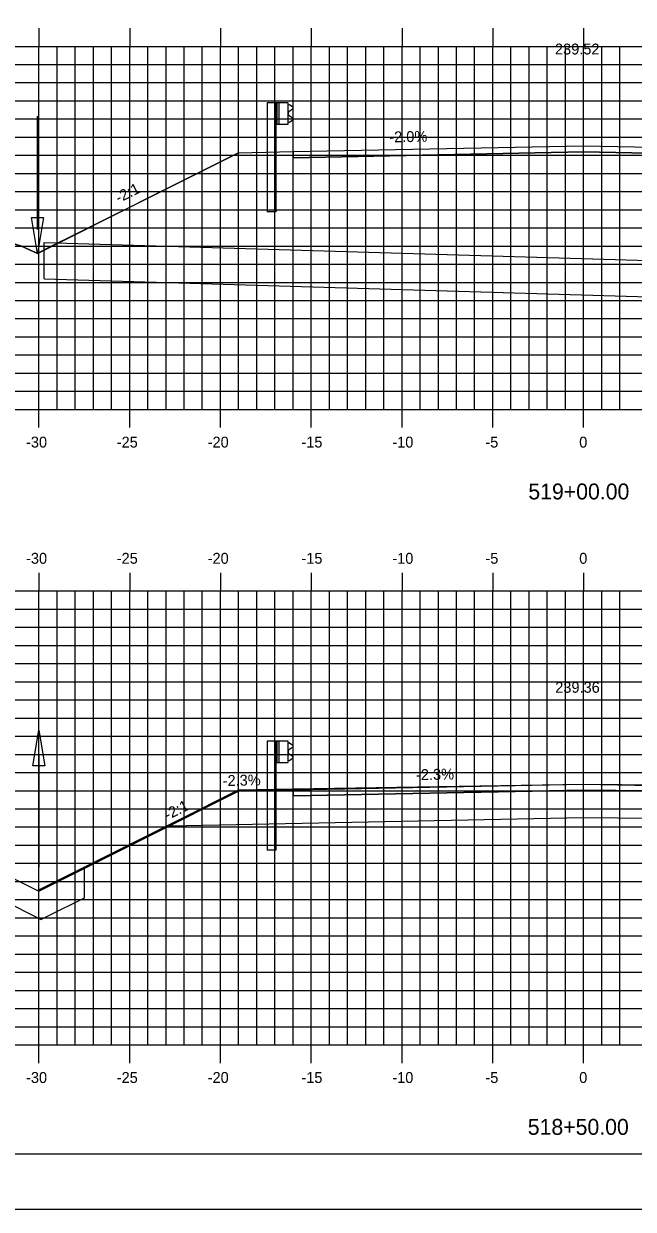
# Model space of a CAD drawing. Extents: x 1170543 to 1177585, y 609599 to 610623.
# Drawn here: x 1173995.7 to 1174029.3, y 609598.8 to 609664.1 of the extents above; entities that cross this region are included whole.
import ezdxf

# ---------------------------------------------------------------- set-up
doc = ezdxf.new("R2010")
doc.units = 0
for name, color, linetype in [('ANNOTATION', 7, 'Continuous'), ('BORDER', 7, 'Continuous'), ('D_Drainage_Culvert', 7, 'Continuous'), ('D_Drainage_Ditch_Line', 7, 'Continuous'), ('D_Guardrail_Beam_Lt', 7, 'Continuous'), ('D_Roadway_Centerline', 7, 'Continuous'), ('D_Roadway_Centerline_Text', 7, 'Continuous'), ('D_Roadway_Edge_Shoulder', 7, 'Continuous'), ('D_Roadway_Edge_TW', 7, 'Continuous'), ('D_Roadway_Pavement', 7, 'Continuous'), ('D_Roadway_SlopeLines', 7, 'Continuous'), ('D_Roadway_SubGrade', 7, 'Continuous'), ('H_V ANNOTATION', 7, 'Continuous'), ('MAJOR', 7, 'Continuous'), ('MINOR', 7, 'Continuous'), ('PATTERNING', 7, 'Continuous'), ('PLOT BOUNDARY', 7, 'Continuous'), ('S_Roadway_Centerline', 7, 'Continuous'), ('SHADING', 7, 'Continuous')]:
    doc.layers.add(name, color=color, linetype=linetype)

msp = doc.modelspace()

# ---------------------------------------------------------------- linework, layer by layer
at = {"layer": 'ANNOTATION'}
for p, q in [((1173994.024, 609617.589), (1173996.524, 609616.339)), ((1173999.024, 609617.589), (1173999.024, 609615.958)), ((1173999.024, 609615.958), (1173997.024, 609614.958)), ((1173997.024, 609614.958), (1173996.655, 609614.774))]:
    msp.add_line(p, q, dxfattribs=at)
msp.add_lwpolyline([(1173994.024, 609617.589), (1173994.024, 609616.089), (1173996.024, 609615.089), (1173996.655, 609614.774)], dxfattribs=at)
at = {"layer": 'BORDER'}
msp.add_line((1173951.531, 609601.872), (1174111.531, 609601.872), dxfattribs=at)
at = {"layer": 'D_Drainage_Culvert'}
for p, q in [((1173996.81, 609652.072), (1174060.21, 609650.172)), ((1173996.81, 609650.072), (1173996.81, 609652.072)), ((1173996.81, 609650.072), (1174060.21, 609648.172))]:
    msp.add_line(p, q, dxfattribs=at)
at = {"layer": 'D_Drainage_Ditch_Line'}
for p, q in [((1173996.447, 609652.782), (1173996.448, 609659.026)), ((1173996.524, 609623.895), (1173996.524, 609617.652))]:
    msp.add_line(p, q, dxfattribs=at)
for points in [[(1173996.119, 609653.439), (1173996.775, 609653.439), (1173996.447, 609651.47)], [(1173996.852, 609623.239), (1173996.196, 609623.239), (1173996.524, 609625.207)]]:
    msp.add_lwpolyline(points, close=True, dxfattribs=at)
at = {"layer": 'D_Guardrail_Beam_Lt'}
for p, q in [((1174009.101, 609659.757), (1174009.101, 609653.757)), ((1174009.572, 609659.757), (1174009.101, 609659.757)), ((1174010.259, 609659.757), (1174009.572, 609659.757)), ((1174009.572, 609659.757), (1174009.572, 609658.591)), ((1174009.634, 609659.757), (1174009.634, 609658.591)), ((1174009.739, 609659.757), (1174009.739, 609658.591)), ((1174010.259, 609658.591), (1174010.259, 609659.757)), ((1174010.259, 609659.674), (1174010.334, 609659.659)), ((1174010.264, 609659.209), (1174010.264, 609659.139)), ((1174010.493, 609659.41), (1174010.298, 609659.273)), ((1174010.349, 609659.653), (1174010.493, 609659.553)), ((1174009.572, 609658.591), (1174010.259, 609658.591)), ((1174009.593, 609653.757), (1174009.593, 609658.591)), ((1174010.334, 609658.689), (1174010.259, 609658.674)), ((1174010.298, 609659.074), (1174010.493, 609658.938)), ((1174010.493, 609658.795), (1174010.349, 609658.695)), ((1174009.593, 609653.757), (1174009.101, 609653.757)), ((1174009.101, 609624.598), (1174009.101, 609618.598)), ((1174009.572, 609624.598), (1174009.101, 609624.598)), ((1174010.259, 609624.598), (1174009.572, 609624.598)), ((1174009.572, 609624.598), (1174009.572, 609623.432)), ((1174009.634, 609624.598), (1174009.634, 609623.432)), ((1174009.739, 609624.598), (1174009.739, 609623.432)), ((1174010.259, 609623.432), (1174010.259, 609624.598)), ((1174010.259, 609624.515), (1174010.334, 609624.5)), ((1174010.264, 609624.05), (1174010.264, 609623.98)), ((1174010.493, 609624.251), (1174010.298, 609624.114)), ((1174010.298, 609623.916), (1174010.493, 609623.779)), ((1174010.349, 609624.494), (1174010.493, 609624.394)), ((1174009.572, 609623.432), (1174010.259, 609623.432)), ((1174009.593, 609618.598), (1174009.593, 609623.432)), ((1174010.334, 609623.53), (1174010.259, 609623.515)), ((1174010.493, 609623.636), (1174010.349, 609623.536)), ((1174009.593, 609618.598), (1174009.101, 609618.598))]:
    msp.add_line(p, q, dxfattribs=at)
for centre, major_axis, start_param, end_param in [((1174010.343, 609659.209), (-0.0789, 0), 5.323254, 6.283185), ((1174010.326, 609659.619), (0.0417, 0), 0.959931, 1.376053), ((1174010.443, 609659.481), (0.0877, 0), 5.323254, 7.243116), ((1174010.343, 609659.139), (-0.0789, 0), 6.283185, 7.243116), ((1174010.326, 609658.729), (0.0417, 0), 4.907132, 5.323254), ((1174010.443, 609658.867), (0.0877, 0), 5.323254, 7.243116), ((1174010.343, 609624.05), (-0.0789, 0), 5.323254, 6.283185), ((1174010.343, 609623.98), (-0.0789, 0), 6.283185, 7.243116), ((1174010.326, 609624.46), (0.0417, 0), 0.959931, 1.376053), ((1174010.443, 609624.322), (0.0877, 0), 5.323254, 7.243116), ((1174010.326, 609623.57), (0.0417, 0), 4.907132, 5.323254), ((1174010.443, 609623.708), (0.0877, 0), 5.323254, 7.243116)]:
    msp.add_ellipse(centre, major_axis=major_axis, ratio=0.995501, start_param=start_param, end_param=end_param, dxfattribs=at)
at = {"layer": 'D_Roadway_Centerline'}
for p, q in [((1174010.53, 609621.913), (1174026.53, 609622.233)), ((1174026.53, 609622.233), (1174042.53, 609622.073)), ((1174002.69, 609619.423), (1174007.53, 609621.843)), ((1174007.53, 609621.843), (1174010.53, 609621.913)), ((1173996.524, 609616.339), (1174002.69, 609619.423))]:
    msp.add_line(p, q, dxfattribs=at)
msp.add_lwpolyline([(1173992.948, 609652.403), (1173993.823, 609652.323), (1173994.698, 609652.141), (1173995.573, 609651.857), (1173996.447, 609651.47), (1174002.669, 609654.581), (1174007.53, 609657.012), (1174010.53, 609657.072), (1174026.53, 609657.392), (1174042.53, 609657.072), (1174045.53, 609657.012), (1174050.391, 609654.581), (1174056.613, 609651.47), (1174062.834, 609648.36)], dxfattribs=at)
at = {"layer": 'D_Roadway_Edge_Shoulder'}
for points in [[(1174010.53, 609657.072), (1174010.53, 609656.738)], [(1174010.53, 609621.913), (1174010.53, 609621.579)]]:
    msp.add_lwpolyline(points, dxfattribs=at)
at = {"layer": 'D_Roadway_Edge_TW'}
for points in [[(1174010.53, 609656.738), (1174010.53, 609657.072), (1174026.53, 609657.392), (1174042.53, 609657.072), (1174042.53, 609656.738), (1174026.53, 609657.058)], [(1174010.53, 609621.579), (1174010.53, 609621.913), (1174026.53, 609622.233), (1174042.53, 609622.073), (1174042.53, 609621.739), (1174026.53, 609621.899)]]:
    msp.add_lwpolyline(points, close=True, dxfattribs=at)
at = {"layer": 'D_Roadway_Pavement'}
for points in [[(1174010.53, 609656.738), (1174010.53, 609656.738), (1174026.53, 609657.058), (1174042.53, 609656.738), (1174042.53, 609656.738), (1174026.53, 609657.058)], [(1174010.53, 609621.579), (1174010.53, 609621.579), (1174026.53, 609621.899), (1174042.53, 609621.739), (1174042.53, 609621.739), (1174026.53, 609621.899)]]:
    msp.add_lwpolyline(points, close=True, dxfattribs=at)
for points in [[(1174010.53, 609656.738), (1174010.53, 609656.738)], [(1174010.53, 609656.738), (1174010.53, 609656.738)], [(1174010.53, 609621.579), (1174010.53, 609621.579)], [(1174010.53, 609621.579), (1174010.53, 609621.579)]]:
    msp.add_lwpolyline(points, dxfattribs=at)
at = {"layer": 'D_Roadway_SlopeLines'}
msp.add_line((1173996.447, 609616.378), (1173996.524, 609616.339), dxfattribs=at)
for points in [[(1174007.53, 609657.012), (1173996.447, 609651.47)], [(1173996.447, 609651.47), (1173995.573, 609651.857), (1173994.698, 609652.141), (1173993.823, 609652.323), (1173992.948, 609652.403)], [(1174007.53, 609621.843), (1173996.524, 609616.339)]]:
    msp.add_lwpolyline(points, dxfattribs=at)
at = {"layer": 'D_Roadway_SubGrade'}
for p, q in [((1174007.53, 609621.843), (1174002.69, 609619.423)), ((1174010.53, 609621.913), (1174007.53, 609621.843)), ((1174010.53, 609620.079), (1174010.53, 609621.913)), ((1174010.53, 609621.579), (1174026.53, 609621.899)), ((1174010.53, 609620.079), (1174010.53, 609621.579)), ((1174026.53, 609621.899), (1174042.53, 609621.739))]:
    msp.add_line(p, q, dxfattribs=at)
at = {"layer": 'MAJOR'}
for p, q in [((1173996.53, 609663.874), (1173996.53, 609662.872)), ((1174001.53, 609663.874), (1174001.53, 609662.872)), ((1174006.53, 609663.874), (1174006.53, 609662.872)), ((1174011.53, 609663.874), (1174011.53, 609662.872)), ((1174016.53, 609663.874), (1174016.53, 609662.872)), ((1174021.53, 609663.874), (1174021.53, 609662.872)), ((1174026.53, 609663.874), (1174026.53, 609662.872)), ((1173956.53, 609662.872), (1174096.53, 609662.872)), ((1173956.53, 609662.872), (1174096.53, 609662.872)), ((1173996.53, 609642.872), (1173996.53, 609662.872)), ((1174001.53, 609642.872), (1174001.53, 609662.872)), ((1174006.53, 609642.872), (1174006.53, 609662.872)), ((1174011.53, 609642.872), (1174011.53, 609662.872)), ((1174016.53, 609642.872), (1174016.53, 609662.872)), ((1174021.53, 609642.872), (1174021.53, 609662.872)), ((1174026.53, 609642.872), (1174026.53, 609662.872)), ((1173956.53, 609657.872), (1174096.53, 609657.872)), ((1173956.53, 609652.872), (1174096.53, 609652.872)), ((1173956.53, 609647.872), (1174096.53, 609647.872)), ((1173956.53, 609642.872), (1174096.53, 609642.872)), ((1173956.53, 609642.872), (1174096.53, 609642.872)), ((1173996.53, 609641.87), (1173996.53, 609642.872)), ((1174001.53, 609641.87), (1174001.53, 609642.872)), ((1174006.53, 609641.87), (1174006.53, 609642.872)), ((1174011.53, 609641.87), (1174011.53, 609642.872)), ((1174016.53, 609641.87), (1174016.53, 609642.872)), ((1174021.53, 609641.87), (1174021.53, 609642.872)), ((1174026.53, 609641.87), (1174026.53, 609642.872)), ((1173996.53, 609633.874), (1173996.53, 609632.872)), ((1174001.53, 609633.874), (1174001.53, 609632.872)), ((1174006.53, 609633.874), (1174006.53, 609632.872)), ((1174011.53, 609633.874), (1174011.53, 609632.872)), ((1174016.53, 609633.874), (1174016.53, 609632.872)), ((1174021.53, 609633.874), (1174021.53, 609632.872)), ((1174026.53, 609633.874), (1174026.53, 609632.872)), ((1173956.53, 609632.872), (1174096.53, 609632.872)), ((1173956.53, 609632.872), (1174096.53, 609632.872)), ((1173996.53, 609607.872), (1173996.53, 609632.872)), ((1174001.53, 609607.872), (1174001.53, 609632.872)), ((1174006.53, 609607.872), (1174006.53, 609632.872)), ((1174011.53, 609607.872), (1174011.53, 609632.872)), ((1174016.53, 609607.872), (1174016.53, 609632.872)), ((1174021.53, 609607.872), (1174021.53, 609632.872)), ((1174026.53, 609607.872), (1174026.53, 609632.872)), ((1173956.53, 609627.872), (1174096.53, 609627.872)), ((1173956.53, 609622.872), (1174096.53, 609622.872)), ((1173956.53, 609617.872), (1174096.53, 609617.872)), ((1173956.53, 609612.872), (1174096.53, 609612.872)), ((1173956.53, 609607.872), (1174096.53, 609607.872)), ((1173956.53, 609607.872), (1174096.53, 609607.872)), ((1173996.53, 609606.87), (1173996.53, 609607.872)), ((1174001.53, 609606.87), (1174001.53, 609607.872)), ((1174006.53, 609606.87), (1174006.53, 609607.872)), ((1174011.53, 609606.87), (1174011.53, 609607.872)), ((1174016.53, 609606.87), (1174016.53, 609607.872)), ((1174021.53, 609606.87), (1174021.53, 609607.872)), ((1174026.53, 609606.87), (1174026.53, 609607.872))]:
    msp.add_line(p, q, dxfattribs=at)
at = {"layer": 'MINOR'}
for p, q in [((1173997.53, 609642.872), (1173997.53, 609662.872)), ((1173998.53, 609642.872), (1173998.53, 609662.872)), ((1173999.53, 609642.872), (1173999.53, 609662.872)), ((1174000.53, 609642.872), (1174000.53, 609662.872)), ((1174002.53, 609642.872), (1174002.53, 609662.872)), ((1174003.53, 609642.872), (1174003.53, 609662.872)), ((1174004.53, 609642.872), (1174004.53, 609662.872)), ((1174005.53, 609642.872), (1174005.53, 609662.872)), ((1174007.53, 609642.872), (1174007.53, 609662.872)), ((1174008.53, 609642.872), (1174008.53, 609662.872)), ((1174009.53, 609642.872), (1174009.53, 609662.872)), ((1174010.53, 609642.872), (1174010.53, 609662.872)), ((1174012.53, 609642.872), (1174012.53, 609662.872)), ((1174013.53, 609642.872), (1174013.53, 609662.872)), ((1174014.53, 609642.872), (1174014.53, 609662.872)), ((1174015.53, 609642.872), (1174015.53, 609662.872)), ((1174017.53, 609642.872), (1174017.53, 609662.872)), ((1174018.53, 609642.872), (1174018.53, 609662.872)), ((1174019.53, 609642.872), (1174019.53, 609662.872)), ((1174020.53, 609642.872), (1174020.53, 609662.872)), ((1174022.53, 609642.872), (1174022.53, 609662.872)), ((1174023.53, 609642.872), (1174023.53, 609662.872)), ((1174024.53, 609642.872), (1174024.53, 609662.872)), ((1174025.53, 609642.872), (1174025.53, 609662.872)), ((1174027.53, 609642.872), (1174027.53, 609662.872)), ((1174028.53, 609642.872), (1174028.53, 609662.872)), ((1173956.53, 609661.872), (1174096.53, 609661.872)), ((1173956.53, 609660.872), (1174096.53, 609660.872)), ((1173956.53, 609659.872), (1174096.53, 609659.872)), ((1173956.53, 609658.872), (1174096.53, 609658.872)), ((1173956.53, 609656.872), (1174096.53, 609656.872)), ((1173956.53, 609655.872), (1174096.53, 609655.872)), ((1173956.53, 609654.872), (1174096.53, 609654.872)), ((1173956.53, 609653.872), (1174096.53, 609653.872)), ((1173956.53, 609651.872), (1174096.53, 609651.872)), ((1173956.53, 609650.872), (1174096.53, 609650.872)), ((1173956.53, 609649.872), (1174096.53, 609649.872)), ((1173956.53, 609648.872), (1174096.53, 609648.872)), ((1173956.53, 609646.872), (1174096.53, 609646.872)), ((1173956.53, 609645.872), (1174096.53, 609645.872)), ((1173956.53, 609644.872), (1174096.53, 609644.872)), ((1173956.53, 609643.872), (1174096.53, 609643.872)), ((1173997.53, 609607.872), (1173997.53, 609632.872)), ((1173998.53, 609607.872), (1173998.53, 609632.872)), ((1173999.53, 609607.872), (1173999.53, 609632.872)), ((1174000.53, 609607.872), (1174000.53, 609632.872)), ((1174002.53, 609607.872), (1174002.53, 609632.872)), ((1174003.53, 609607.872), (1174003.53, 609632.872)), ((1174004.53, 609607.872), (1174004.53, 609632.872)), ((1174005.53, 609607.872), (1174005.53, 609632.872)), ((1174007.53, 609607.872), (1174007.53, 609632.872)), ((1174008.53, 609607.872), (1174008.53, 609632.872)), ((1174009.53, 609607.872), (1174009.53, 609632.872)), ((1174010.53, 609607.872), (1174010.53, 609632.872)), ((1174012.53, 609607.872), (1174012.53, 609632.872)), ((1174013.53, 609607.872), (1174013.53, 609632.872)), ((1174014.53, 609607.872), (1174014.53, 609632.872)), ((1174015.53, 609607.872), (1174015.53, 609632.872)), ((1174017.53, 609607.872), (1174017.53, 609632.872)), ((1174018.53, 609607.872), (1174018.53, 609632.872)), ((1174019.53, 609607.872), (1174019.53, 609632.872)), ((1174020.53, 609607.872), (1174020.53, 609632.872)), ((1174022.53, 609607.872), (1174022.53, 609632.872)), ((1174023.53, 609607.872), (1174023.53, 609632.872)), ((1174024.53, 609607.872), (1174024.53, 609632.872)), ((1174025.53, 609607.872), (1174025.53, 609632.872)), ((1174027.53, 609607.872), (1174027.53, 609632.872)), ((1174028.53, 609607.872), (1174028.53, 609632.872)), ((1173956.53, 609631.872), (1174096.53, 609631.872)), ((1173956.53, 609630.872), (1174096.53, 609630.872)), ((1173956.53, 609629.872), (1174096.53, 609629.872)), ((1173956.53, 609628.872), (1174096.53, 609628.872)), ((1173956.53, 609626.872), (1174096.53, 609626.872)), ((1173956.53, 609625.872), (1174096.53, 609625.872)), ((1173956.53, 609624.872), (1174096.53, 609624.872)), ((1173956.53, 609623.872), (1174096.53, 609623.872)), ((1173956.53, 609621.872), (1174096.53, 609621.872)), ((1173956.53, 609620.872), (1174096.53, 609620.872)), ((1173956.53, 609619.872), (1174096.53, 609619.872)), ((1173956.53, 609618.872), (1174096.53, 609618.872)), ((1173956.53, 609616.872), (1174096.53, 609616.872)), ((1173956.53, 609615.872), (1174096.53, 609615.872)), ((1173956.53, 609614.872), (1174096.53, 609614.872)), ((1173956.53, 609613.872), (1174096.53, 609613.872)), ((1173956.53, 609611.872), (1174096.53, 609611.872)), ((1173956.53, 609610.872), (1174096.53, 609610.872)), ((1173956.53, 609609.872), (1174096.53, 609609.872)), ((1173956.53, 609608.872), (1174096.53, 609608.872))]:
    msp.add_line(p, q, dxfattribs=at)
at = {"layer": 'PATTERNING'}
msp.add_lwpolyline([(1173996.524, 609616.339), (1173998.524, 609617.339), (1173999.024, 609617.589)], dxfattribs=at)
at = {"layer": 'PLOT BOUNDARY'}
msp.add_lwpolyline([(1173943.437, 609598.813), (1174113.437, 609598.813), (1174113.437, 609708.813), (1173943.437, 609708.813)], close=True, dxfattribs=at)
at = {"layer": 'S_Roadway_Centerline'}
for points in [[(1173995.574, 609651.857), (1173996.448, 609651.471), (1173997.198, 609651.86), (1173997.833, 609652.175), (1173997.855, 609652.173), (1173997.855, 609652.173), (1173997.855, 609652.173), (1173997.855, 609652.173), (1173997.855, 609652.173), (1173997.855, 609652.173), (1173997.855, 609652.173), (1173997.855, 609652.173), (1173997.855, 609652.173), (1174004.145, 609655.318), (1174004.145, 609655.318), (1174007.53, 609657.011), (1174007.53, 609657.011), (1174010.53, 609657.071), (1174010.53, 609657.071), (1174026.53, 609657.391), (1174026.53, 609657.391), (1174042.53, 609657.071)], [(1173991.629, 609618.787), (1173996.448, 609616.377), (1173996.448, 609616.377), (1174002.834, 609619.57), (1174002.834, 609619.57), (1174002.834, 609619.57), (1174002.834, 609619.57), (1174004.199, 609620.253), (1174004.199, 609620.253), (1174007.53, 609621.918), (1174007.53, 609621.918), (1174007.53, 609621.918), (1174010.53, 609621.978), (1174026.53, 609622.232), (1174026.53, 609622.232), (1174026.531, 609622.232), (1174042.53, 609621.912)]]:
    msp.add_lwpolyline(points, dxfattribs=at)
at = {"layer": 'SHADING'}
msp.add_lwpolyline([(1174003.732, 609619.943), (1174026.53, 609620.399), (1174049.211, 609620.173)], dxfattribs=at)

# ---------------------------------------------------------------- texts
at = {"layer": 'ANNOTATION'}
for s, rotation, p in [('-2.0%', 1.14576, (1174015.833, 609657.578)), ('-2:1', 26.56505, (1174000.918, 609654.223)), ('-2.3%', 1.33666, (1174006.657, 609622.122)), ('-2.3%', 1.14576, (1174017.307, 609622.448)), ('-2:1', 26.56505, (1174003.611, 609620.231))]:
    msp.add_text(s, height=0.6, rotation=rotation, dxfattribs=at).set_placement(p)
at = {"layer": 'D_Roadway_Centerline'}
for s, p in [('C', (1174026.525, 609657.392)), ('L', (1174026.53, 609657.384)), ('C', (1174026.525, 609622.233)), ('L', (1174026.53, 609622.225))]:
    msp.add_text(s, height=0.0146, dxfattribs=at).set_placement(p)
at = {"layer": 'D_Roadway_Centerline_Text'}
for s, p in [('239.52', (1174024.954, 609662.424)), ('239.36', (1174024.968, 609627.265))]:
    msp.add_text(s, height=0.6, dxfattribs=at).set_placement(p)
at = {"layer": 'H_V ANNOTATION'}
for s, height, p in [('-30', 0.6, (1173995.819, 609640.772)), ('-25', 0.6, (1174000.816, 609640.772)), ('-20', 0.6, (1174005.824, 609640.772)), ('-15', 0.6, (1174010.987, 609640.772)), ('-10', 0.6, (1174015.995, 609640.772)), ('-5', 0.6, (1174021.121, 609640.772)), ('0', 0.6, (1174026.289, 609640.772)), ('519+00.00', 0.875, (1174023.487, 609637.915)), ('-30', 0.6, (1173995.819, 609634.372)), ('-25', 0.6, (1174000.816, 609634.372)), ('-20', 0.6, (1174005.824, 609634.372)), ('-15', 0.6, (1174010.987, 609634.372)), ('-10', 0.6, (1174015.995, 609634.372)), ('-5', 0.6, (1174021.121, 609634.372)), ('0', 0.6, (1174026.289, 609634.372)), ('-30', 0.6, (1173995.819, 609605.772)), ('-25', 0.6, (1174000.816, 609605.772)), ('-20', 0.6, (1174005.824, 609605.772)), ('-15', 0.6, (1174010.987, 609605.772)), ('-10', 0.6, (1174015.995, 609605.772)), ('-5', 0.6, (1174021.121, 609605.772)), ('0', 0.6, (1174026.289, 609605.772)), ('518+50.00', 0.875, (1174023.456, 609602.915))]:
    msp.add_text(s, height=height, dxfattribs=at).set_placement(p)

doc.saveas('drawing.dxf')
